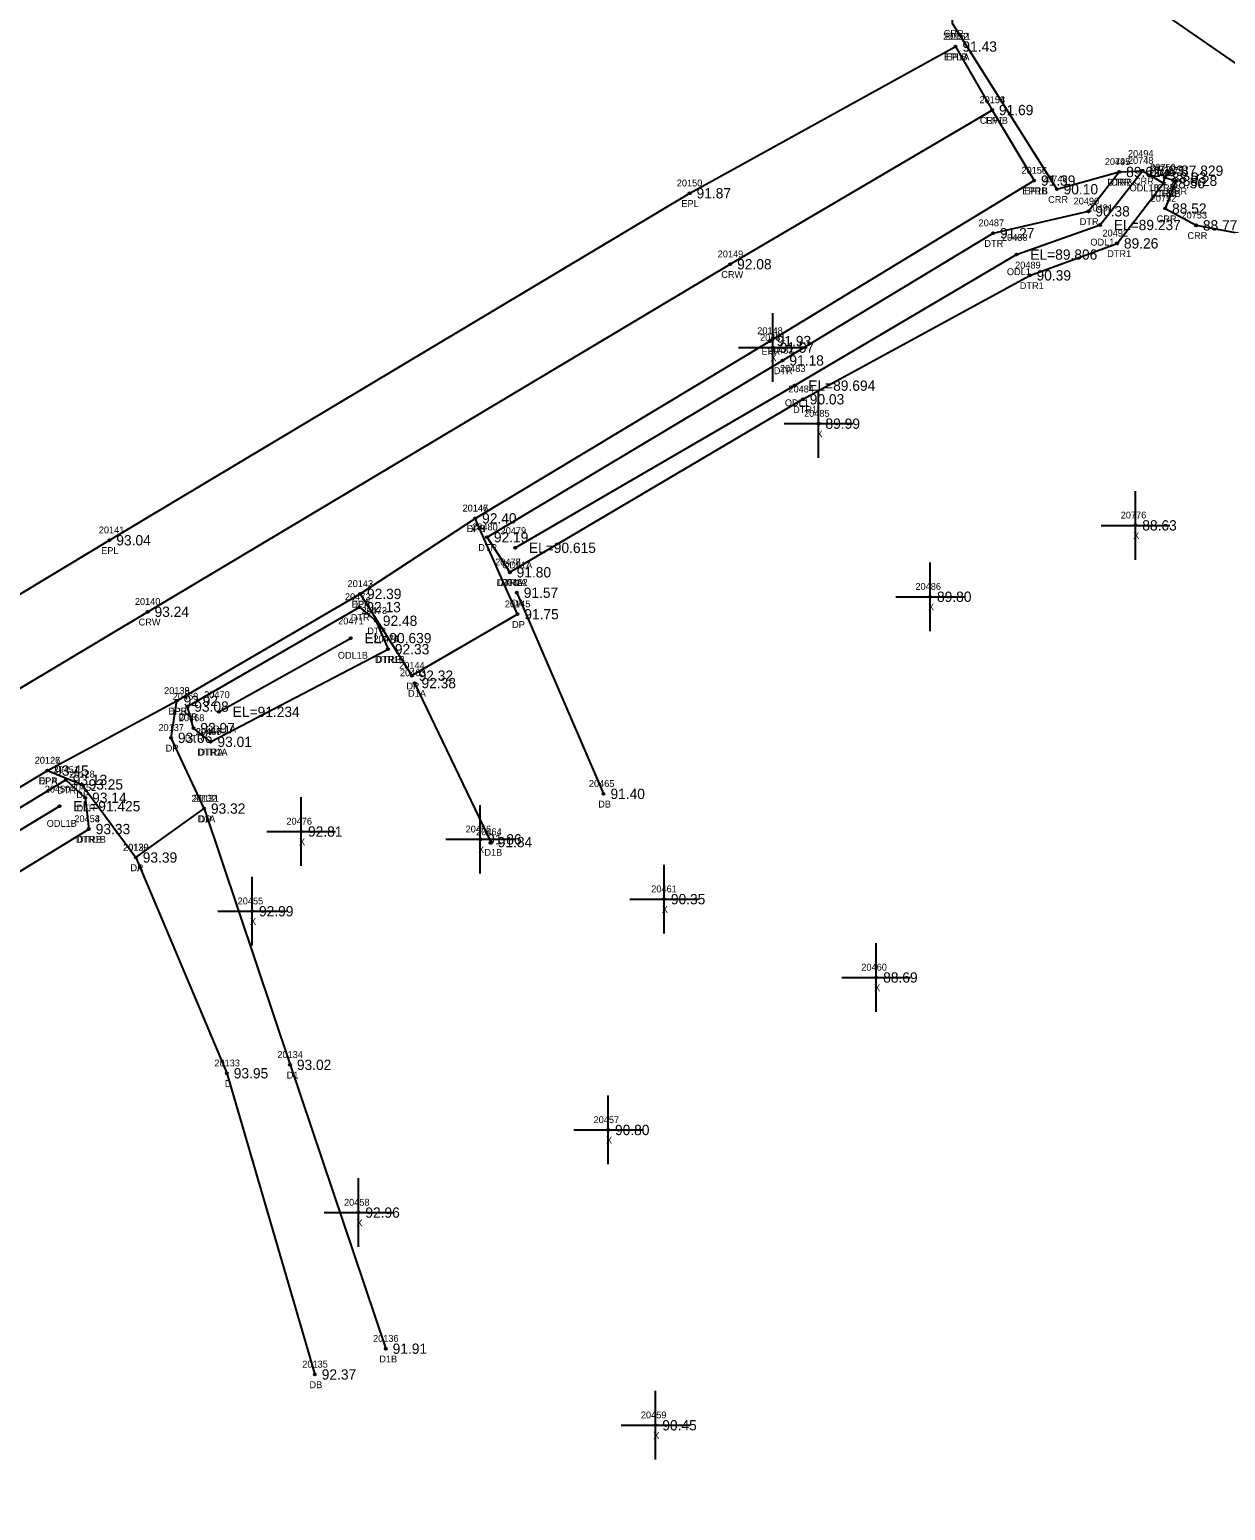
# Model space of a CAD drawing. Extents: x 2530197 to 2532051, y 935230 to 936631.
# Drawn here: x 2530944.6 to 2531118.7, y 935734.5 to 935950.2 of the extents above; entities that cross this region are included whole.
import ezdxf

# ---------------------------------------------------------------- set-up
doc = ezdxf.new("R2010")
doc.units = 0
for name, color, linetype in [('RD_DTM_BkLn1', 7, 'Continuous'), ('RD_EX_Driveway', 7, 'Continuous'), ('RD_EX_Driveway_txCode', 7, 'Continuous'), ('RD_EX_H2O', 7, 'Continuous'), ('RD_EX_H2O_txCode', 7, 'Continuous'), ('RD_EX_Misc', 7, 'Continuous'), ('RD_EX_Misc_txCode', 7, 'Continuous'), ('RD_EX_Road', 7, 'Continuous'), ('RD_EX_Road_txCode', 7, 'Continuous'), ('RD_EX_TX_Driveway_ELEV', 7, 'Continuous'), ('RD_EX_TX_H2O_ELEV', 7, 'Continuous'), ('RD_EX_TX_Misc_ELEV', 7, 'Continuous'), ('RD_EX_TX_Road_ELEV', 7, 'Continuous'), ('RD_HC_Survey_ELEV', 7, 'Continuous'), ('RD_HC_Survey_txCode', 7, 'Continuous'), ('RD_SMD_Locator', 7, 'Continuous')]:
    doc.layers.add(name, color=color, linetype=linetype)

msp = doc.modelspace()

# ---------------------------------------------------------------- linework, layer by layer
at = {"layer": 'RD_DTM_BkLn1'}
msp.add_lwpolyline([(2530212.5, 935590.24), (2530312.97, 935590.25), (2530414.21, 935590.57), (2530470.01, 935593.88), (2530526.51, 935611.77), (2530574.01, 935635.84), (2530615.35, 935659.73), (2530701.7, 935710.7), (2530789.3, 935762.35), (2530874.46, 935813.14), (2530961.78, 935865.4), (2531046.63, 935916.04), (2531084.76, 935938.51)], dxfattribs=at)
at = {"layer": 'RD_EX_Driveway'}
for p, q in [((2531015.55, 935868.18), (2531028.18, 935838.87)), ((2531000.66, 935855.01), (2531011.76, 935831.84))]:
    msp.add_line(p, q, dxfattribs=at)
for points in [[(2530992.72, 935868), (2531000.24, 935856.09), (2531015.63, 935865.04), (2531009.49, 935879.01)], [(2530947.17, 935842.26), (2530952.17, 935840.24), (2530960.06, 935829.59), (2530969.99, 935836.72), (2530965.18, 935847.03), (2530966, 935852.42)], [(2530969.99, 935836.72), (2530982.51, 935799.38), (2530996.46, 935758.02)], [(2530960.06, 935829.59), (2530973.32, 935798.15), (2530986.13, 935754.26)]]:
    msp.add_lwpolyline(points, dxfattribs=at)
at = {"layer": 'RD_EX_H2O'}
for p, q in [((2530970.94, 935846.45), (2530996.78, 935859.95)), ((2530972.16, 935850.82), (2530991.35, 935861.56)), ((2530886.58, 935799.6), (2530948.95, 935837.06))]:
    msp.add_line(p, q, dxfattribs=at)
for points in [[(2531095.07, 935962.75), (2531122.05, 935944.01), (2531139.42, 935896.32), (2531161, 935756.43), (2531179.99, 935655.36), (2531191.29, 935570.65), (2531207.98, 935448.59)], [(2531078.88, 935952.28), (2531078.96, 935951.18), (2531094.18, 935926.97), (2531103.29, 935929.49), (2531106.67, 935929.67), (2531109.75, 935927.85), (2531109.94, 935928.67), (2531111.53, 935928.19), (2531109.98, 935924.15), (2531114.47, 935921.71), (2531121.2, 935920.45), (2531134.65, 935891.6), (2531155.43, 935754.46), (2531173.73, 935652.91), (2531186.19, 935572.51), (2531201.43, 935446.7)], [(2531014.51, 935871.15), (2531011.2, 935876.26), (2531054.24, 935902.02), (2531084.91, 935920.57), (2531098.8, 935923.75), (2531103.29, 935929.49)], [(2531015.3, 935874.72), (2531055.99, 935898.35), (2531088.33, 935917.45), (2531100.49, 935921.76), (2531106.67, 935929.67)], [(2531014.51, 935871.15), (2531057.21, 935896.36), (2531090.24, 935914.42), (2531102.96, 935919.08), (2531109.75, 935927.85)], [(2530970.94, 935846.45), (2530968.45, 935848.45), (2530967.56, 935851.58), (2530992.63, 935866.08), (2530995.03, 935864.09), (2530996.78, 935859.95)], [(2530882.81, 935800.19), (2530949.87, 935840.9), (2530952.69, 935838.3), (2530953.21, 935833.74)], [(2530882.81, 935800.19), (2530888.21, 935794.65), (2530891.36, 935795.84), (2530953.21, 935833.74)]]:
    msp.add_lwpolyline(points, dxfattribs=at)
at = {"layer": 'RD_EX_Misc'}
for p, q in [((2531052.81, 935898.89), (2531052.81, 935908.89)), ((2531047.81, 935903.89), (2531057.81, 935903.89)), ((2531059.5, 935887.81), (2531059.5, 935897.81)), ((2531054.5, 935892.81), (2531064.5, 935892.81)), ((2531105.64, 935872.99), (2531105.64, 935882.99)), ((2531100.64, 935877.99), (2531110.64, 935877.99)), ((2531075.74, 935862.59), (2531075.74, 935872.59)), ((2531070.74, 935867.59), (2531080.74, 935867.59)), ((2530984.13, 935828.38), (2530984.13, 935838.38)), ((2531010.22, 935827.24), (2531010.22, 935837.24)), ((2530979.13, 935833.38), (2530989.13, 935833.38)), ((2531005.22, 935832.24), (2531015.22, 935832.24)), ((2531036.98, 935818.52), (2531036.98, 935828.52)), ((2530976.99, 935816.76), (2530976.99, 935826.76)), ((2531031.98, 935823.52), (2531041.98, 935823.52)), ((2530971.99, 935821.76), (2530981.99, 935821.76)), ((2531067.9, 935807.11), (2531067.9, 935817.11)), ((2531062.9, 935812.11), (2531072.9, 935812.11)), ((2531028.84, 935784.89), (2531028.84, 935794.89)), ((2531023.84, 935789.89), (2531033.84, 935789.89)), ((2530992.48, 935772.85), (2530992.48, 935782.85)), ((2530987.48, 935777.85), (2530997.48, 935777.85)), ((2531035.73, 935741.86), (2531035.73, 935751.86)), ((2531030.73, 935746.86), (2531040.73, 935746.86))]:
    msp.add_line(p, q, dxfattribs=at)
at = {"layer": 'RD_EX_Road'}
for points in [[(2530213.13, 935600.16), (2530313.8, 935600.81), (2530414.15, 935601.13), (2530426.72, 935601.43), (2530429.46, 935603.55), (2530467.67, 935608.62), (2530486.46, 935612.38), (2530518.02, 935622.55), (2530522.16, 935623.68), (2530567.91, 935646.01), (2530609.3, 935670.15), (2530695.46, 935720.02), (2530775.85, 935769.27), (2530868.29, 935824.03), (2530924.84, 935856.95), (2530956.21, 935875.82), (2531040.72, 935926.38), (2531079.45, 935947.76)], [(2531079.45, 935947.76), (2531084.76, 935938.51), (2531090.88, 935928.23)], [(2530212.44, 935579.72), (2530312.61, 935580.14), (2530402.98, 935580.64), (2530451.06, 935579.53), (2530466.91, 935580.35), (2530487.45, 935583.29), (2530533.43, 935598.45), (2530580.28, 935625.08), (2530621.69, 935649.23), (2530704.62, 935698.35), (2530718.67, 935706.38), (2530795.45, 935752.36), (2530871.33, 935796.67), (2530882.4, 935803.04), (2530947.17, 935842.26), (2530966, 935852.42), (2530992.72, 935868), (2531009.49, 935879.01), (2531052.39, 935904.85), (2531090.88, 935928.23)]]:
    msp.add_lwpolyline(points, dxfattribs=at)
at = {"layer": 'RD_SMD_Locator'}
for centre in [(2531079.45, 935947.76), (2531079.45, 935947.76), (2531084.76, 935938.51), (2531084.76, 935938.51), (2531103.29, 935929.49), (2531103.29, 935929.49), (2531106.67, 935929.67), (2531106.67, 935929.67), (2531109.94, 935928.67), (2531040.72, 935926.38), (2531090.88, 935928.23), (2531090.88, 935928.23), (2531094.18, 935926.97), (2531109.75, 935927.85), (2531109.75, 935927.85), (2531111.53, 935928.19), (2531109.98, 935924.15), (2531098.8, 935923.75), (2531084.91, 935920.57), (2531100.49, 935921.76), (2531114.47, 935921.71), (2531102.96, 935919.08), (2531046.63, 935916.04), (2531088.33, 935917.45), (2531090.24, 935914.42), (2531052.39, 935904.85), (2531052.81, 935903.89), (2531054.24, 935902.02), (2531055.99, 935898.35), (2531057.21, 935896.36), (2531059.5, 935892.81), (2531009.49, 935879.01), (2531009.49, 935879.01), (2531105.64, 935877.99), (2530956.21, 935875.82), (2531011.2, 935876.26), (2531015.3, 935874.72), (2531014.51, 935871.15), (2531014.51, 935871.15), (2530992.72, 935868), (2530992.72, 935868), (2531015.55, 935868.18), (2530992.63, 935866.08), (2531075.74, 935867.59), (2530961.78, 935865.4), (2530995.03, 935864.09), (2531015.63, 935865.04), (2530991.35, 935861.56), (2530996.78, 935859.95), (2530996.78, 935859.95), (2531000.24, 935856.09), (2531000.66, 935855.01), (2530966, 935852.42), (2530966, 935852.42), (2530967.56, 935851.58), (2530972.16, 935850.82), (2530965.18, 935847.03), (2530968.45, 935848.45), (2530970.94, 935846.45), (2530970.94, 935846.45), (2530947.17, 935842.26), (2530947.17, 935842.26), (2530949.87, 935840.9), (2530952.17, 935840.24), (2530952.69, 935838.3), (2531028.18, 935838.87), (2530948.95, 935837.06), (2530969.99, 935836.72), (2530969.99, 935836.72), (2530953.21, 935833.74), (2530953.21, 935833.74), (2530984.13, 935833.38), (2531010.22, 935832.24), (2531011.76, 935831.84), (2530960.06, 935829.59), (2530960.06, 935829.59), (2531036.98, 935823.52), (2530976.99, 935821.76), (2531067.9, 935812.11), (2530982.51, 935799.38), (2530973.32, 935798.15), (2531028.84, 935789.89), (2530992.48, 935777.85), (2530996.46, 935758.02), (2530986.13, 935754.26), (2531035.73, 935746.86)]:
    msp.add_circle(centre, 0.15, dxfattribs=at)

# ---------------------------------------------------------------- texts
at = {"layer": 'RD_EX_Driveway_txCode'}
for s, p in [('20146', (2531007.63, 935880.01)), ('DPB', (2531008.24, 935877.01)), ('20143', (2530990.89, 935869)), ('20462', (2531013.41, 935869.18)), ('DPA', (2530991.46, 935866)), ('20145', (2531013.8, 935866.04)), ('DA', (2531014.76, 935866.18)), ('DP', (2531014.85, 935863.04)), ('20144', (2530998.4, 935857.09)), ('20463', (2530998.52, 935856.01)), ('20138', (2530964.17, 935853.42)), ('DP', (2530999.46, 935854.09)), ('D1A', (2530999.7, 935853.01)), ('DPB', (2530964.75, 935850.42)), ('20137', (2530963.34, 935848.03)), ('DP', (2530964.4, 935845.03)), ('20127', (2530945.33, 935843.26)), ('20128', (2530950.34, 935841.24)), ('DPA', (2530945.9, 935840.26)), ('20465', (2531026.04, 935839.87)), ('DP', (2530951.39, 935838.24)), ('20132', (2530968.16, 935837.72)), ('20131', (2530968.44, 935837.72)), ('D1A', (2530969.03, 935834.72)), ('DP', (2530969.21, 935834.72)), ('DB', (2531027.4, 935836.87)), ('20464', (2531009.62, 935832.84)), ('20130', (2530958.18, 935830.59)), ('20129', (2530958.22, 935830.59)), ('D1B', (2531010.82, 935829.84)), ('DA', (2530959.26, 935827.59)), ('DP', (2530959.28, 935827.59)), ('20134', (2530980.67, 935800.38)), ('20133', (2530971.49, 935799.15)), ('D', (2530973.02, 935796.15)), ('D1', (2530982.03, 935797.38)), ('20136', (2530994.6, 935759.02)), ('20135', (2530984.3, 935755.26)), ('D1B', (2530995.51, 935756.02)), ('DB', (2530985.35, 935752.26))]:
    msp.add_text(s, height=1, dxfattribs=at).set_placement(p)
at = {"layer": 'RD_EX_H2O_txCode'}
for s, p in [('CRR', (2531077.71, 935949.18)), ('20495', (2531101.18, 935930.49)), ('20747', (2531101.18, 935930.49)), ('20494', (2531104.55, 935931.67)), ('20748', (2531104.55, 935930.67)), ('20750', (2531107.78, 935929.67)), ('20746', (2531092.04, 935927.97)), ('CRR', (2531102.04, 935927.49)), ('CRR', (2531105.42, 935927.67)), ('20493', (2531107.63, 935928.85)), ('20749', (2531107.63, 935928.85)), ('20751', (2531109.69, 935929.19)), ('DTRB', (2531101.55, 935927.49)), ('ODL1B', (2531104.79, 935926.67)), ('DTR1B', (2531107.85, 935925.85)), ('CRR', (2531108.5, 935925.85)), ('CRR', (2531108.69, 935926.67)), ('CRR', (2531110.28, 935926.19)), ('CRR', (2531092.93, 935924.97)), ('20490', (2531096.64, 935924.75)), ('20491', (2531098.65, 935923.76)), ('20752', (2531107.87, 935925.15)), ('20487', (2531082.79, 935921.57)), ('DTR', (2531097.53, 935921.75)), ('CRR', (2531108.73, 935922.15)), ('20753', (2531112.35, 935922.71)), ('20488', (2531086.21, 935919.45)), ('20492', (2531100.84, 935920.08)), ('CRR', (2531113.22, 935919.71)), ('DTR', (2531083.64, 935918.57)), ('ODL1', (2531099.08, 935918.76)), ('DTR1', (2531101.53, 935917.08)), ('20489', (2531088.12, 935915.42)), ('ODL1', (2531086.92, 935914.45)), ('DTR1', (2531088.8, 935912.42)), ('20482', (2531052.12, 935903.02)), ('DTR', (2531052.97, 935900.02)), ('20483', (2531053.87, 935900.35)), ('20484', (2531055.1, 935897.36)), ('ODL1', (2531054.58, 935895.35)), ('DTR1', (2531055.78, 935894.36)), ('20480', (2531009.04, 935877.26)), ('20479', (2531013.18, 935876.72)), ('DTR', (2531009.93, 935874.26)), ('20477', (2531012.39, 935872.15)), ('20478', (2531012.39, 935872.15)), ('ODL1A', (2531013.4, 935871.72)), ('20472', (2530990.51, 935867.08)), ('DTR1A', (2531012.59, 935869.15)), ('DTRA', (2531012.76, 935869.15)), ('20473', (2530992.91, 935865.09)), ('20471', (2530989.52, 935863.56)), ('DTR', (2530991.36, 935864.08)), ('DTR', (2530993.76, 935862.09)), ('20474', (2530994.66, 935860.95)), ('20475', (2530994.66, 935860.95)), ('ODL1B', (2530989.47, 935858.56)), ('DTR1B', (2530994.87, 935857.95)), ('DTRB', (2530995.04, 935857.95)), ('20469', (2530965.42, 935852.58)), ('20470', (2530970, 935852.82)), ('20468', (2530966.31, 935849.45)), ('DTR', (2530966.29, 935849.58)), ('ODL1A', (2530970.26, 935847.82)), ('DTR', (2530967.18, 935846.45)), ('20466', (2530968.77, 935847.45)), ('20467', (2530968.8, 935847.45)), ('DTR1A', (2530969.02, 935844.45)), ('DTRA', (2530969.18, 935844.45)), ('20451', (2530948.04, 935841.9)), ('20450', (2530946.79, 935839.06)), ('20452', (2530950.57, 935839.3)), ('DTR', (2530948.61, 935838.9)), ('20453', (2530951.1, 935834.74)), ('20454', (2530951.1, 935834.74)), ('DTR', (2530951.42, 935836.3)), ('ODL1B', (2530947.07, 935834.06)), ('DTR1B', (2530951.31, 935831.74)), ('DTRB', (2530951.47, 935831.74))]:
    msp.add_text(s, height=1, dxfattribs=at).set_placement(p)
at = {"layer": 'RD_EX_Misc_txCode'}
for s, p in [('20481', (2531050.97, 935904.89)), ('X', (2531052.49, 935901.89)), ('20485', (2531057.38, 935893.81)), ('X', (2531059.19, 935890.81)), ('20776', (2531103.5, 935878.99)), ('X', (2531105.32, 935875.99)), ('20486', (2531073.6, 935868.59)), ('X', (2531075.43, 935865.59)), ('20476', (2530981.99, 935834.38)), ('20456', (2531008.08, 935833.24)), ('X', (2530983.81, 935831.38)), ('X', (2531009.9, 935830.24)), ('20461', (2531035.12, 935824.52)), ('20455', (2530974.88, 935822.76)), ('X', (2530976.68, 935819.76)), ('X', (2531036.66, 935821.52)), ('20460', (2531065.72, 935813.11)), ('X', (2531067.58, 935810.11)), ('20457', (2531026.72, 935790.89)), ('X', (2531028.53, 935787.89)), ('20458', (2530990.37, 935778.85)), ('X', (2530992.17, 935775.85)), ('20459', (2531033.61, 935747.86)), ('X', (2531035.42, 935744.86))]:
    msp.add_text(s, height=1, dxfattribs=at).set_placement(p)
at = {"layer": 'RD_EX_Road_txCode'}
for s, p in [('20152', (2531077.62, 935948.76)), ('20151', (2531077.9, 935948.76)), ('EPLB', (2531077.77, 935945.76)), ('EP1A', (2531078.04, 935945.76)), ('20153', (2531082.93, 935939.51)), ('EP1', (2531083.84, 935936.51)), ('20156', (2531089.03, 935929.23)), ('20155', (2531089.05, 935929.23)), ('20150', (2531038.84, 935927.38)), ('EPRB', (2531089.18, 935926.23)), ('EP1B', (2531089.49, 935926.23)), ('EPL', (2531039.51, 935924.38)), ('20148', (2531050.56, 935905.85)), ('EPR', (2531051.17, 935902.85)), ('20147', (2531007.65, 935880.01)), ('20141', (2530954.66, 935876.82)), ('EPR', (2531008.26, 935877.01)), ('EPL', (2530955, 935873.82)), ('20142', (2530990.89, 935869)), ('EPR', (2530991.5, 935866)), ('20139', (2530964.17, 935853.42)), ('EPR', (2530964.77, 935850.42)), ('20126', (2530945.31, 935843.26)), ('EPR', (2530945.94, 935840.26))]:
    msp.add_text(s, height=1, dxfattribs=at).set_placement(p)
at = {"layer": 'RD_EX_TX_Driveway_ELEV'}
for s, p in [('92.40', (2531010.49, 935878.26)), ('92.39', (2530993.72, 935867.25)), ('91.57', (2531016.55, 935867.43)), ('91.75', (2531016.63, 935864.29)), ('92.32', (2531001.24, 935855.34)), ('92.38', (2531001.66, 935854.26)), ('92.92', (2530967, 935851.67)), ('93.06', (2530966.18, 935846.28)), ('93.45', (2530948.17, 935841.51)), ('93.25', (2530953.17, 935839.49)), ('91.40', (2531029.18, 935838.12)), ('93.32', (2530970.99, 935835.97)), ('93.32', (2530970.99, 935835.97)), ('91.84', (2531012.76, 935831.09)), ('93.39', (2530961.06, 935828.84)), ('93.39', (2530961.06, 935828.84)), ('93.02', (2530983.51, 935798.63)), ('93.95', (2530974.32, 935797.4)), ('91.91', (2530997.46, 935757.27)), ('92.37', (2530987.13, 935753.51))]:
    msp.add_text(s, height=1.5, dxfattribs=at).set_placement(p)
at = {"layer": 'RD_EX_TX_H2O_ELEV'}
for s, p in [('89.62', (2531104.29, 935928.74)), ('89.62', (2531104.29, 935928.74)), ('87.83', (2531107.67, 935928.92)), ('EL=87.829', (2531108.67, 935928.92)), ('88.56', (2531110.75, 935927.1)), ('88.56', (2531110.75, 935927.1)), ('88.03', (2531110.94, 935927.92)), ('88.28', (2531112.53, 935927.44)), ('90.10', (2531095.18, 935926.22)), ('90.38', (2531099.8, 935923)), ('88.52', (2531110.98, 935923.4)), ('EL=89.237', (2531102.49, 935921.01)), ('88.77', (2531115.47, 935920.96)), ('91.27', (2531085.91, 935919.82)), ('EL=89.806', (2531090.33, 935916.7)), ('89.26', (2531103.96, 935918.33)), ('90.39', (2531091.24, 935913.67)), ('91.18', (2531055.24, 935901.27)), ('EL=89.694', (2531057.99, 935897.6)), ('90.03', (2531058.21, 935895.61)), ('92.19', (2531012.2, 935875.51)), ('EL=90.615', (2531017.3, 935873.97)), ('91.80', (2531015.51, 935870.4)), ('91.80', (2531015.51, 935870.4)), ('92.13', (2530993.63, 935865.33)), ('92.48', (2530996.03, 935863.34)), ('EL=90.639', (2530993.35, 935860.81)), ('92.33', (2530997.78, 935859.2)), ('92.33', (2530997.78, 935859.2)), ('93.08', (2530968.56, 935850.83)), ('EL=91.234', (2530974.16, 935850.07)), ('92.97', (2530969.45, 935847.7)), ('93.01', (2530971.94, 935845.7)), ('93.01', (2530971.94, 935845.7)), ('93.13', (2530950.87, 935840.15)), ('93.14', (2530953.69, 935837.55)), ('EL=91.425', (2530950.95, 935836.31)), ('93.33', (2530954.21, 935832.99)), ('93.33', (2530954.21, 935832.99))]:
    msp.add_text(s, height=1.5, dxfattribs=at).set_placement(p)
at = {"layer": 'RD_EX_TX_Misc_ELEV'}
for s, p in [('91.57', (2531053.81, 935903.14)), ('89.99', (2531060.5, 935892.06)), ('88.63', (2531106.64, 935877.24)), ('89.80', (2531076.74, 935866.84)), ('92.81', (2530985.13, 935832.63)), ('91.86', (2531011.22, 935831.49)), ('90.35', (2531037.98, 935822.77)), ('92.99', (2530977.99, 935821.01)), ('88.69', (2531068.9, 935811.36)), ('90.80', (2531029.84, 935789.14)), ('92.96', (2530993.48, 935777.1)), ('90.45', (2531036.73, 935746.11))]:
    msp.add_text(s, height=1.5, dxfattribs=at).set_placement(p)
at = {"layer": 'RD_EX_TX_Road_ELEV'}
for s, p in [('91.43', (2531080.45, 935947.01)), ('91.43', (2531080.45, 935947.01)), ('91.69', (2531085.76, 935937.76)), ('91.39', (2531091.88, 935927.48)), ('91.39', (2531091.88, 935927.48)), ('91.87', (2531041.72, 935925.63)), ('91.93', (2531053.39, 935904.1)), ('92.40', (2531010.49, 935878.26)), ('93.04', (2530957.21, 935875.07)), ('92.39', (2530993.72, 935867.25)), ('92.92', (2530967, 935851.67)), ('93.45', (2530948.17, 935841.51))]:
    msp.add_text(s, height=1.5, dxfattribs=at).set_placement(p)
at = {"layer": 'RD_HC_Survey_ELEV'}
for s, p in [('91.69', (2531085.76, 935937.76)), ('92.08', (2531047.63, 935915.29)), ('93.24', (2530962.78, 935864.65))]:
    msp.add_text(s, height=1.5, dxfattribs=at).set_placement(p)
at = {"layer": 'RD_HC_Survey_txCode'}
for s, p in [('20154', (2531082.93, 935939.51)), ('CRWB', (2531082.98, 935936.51)), ('20149', (2531044.8, 935917.04)), ('CRW', (2531045.32, 935914.04)), ('20140', (2530959.91, 935866.4)), ('CRW', (2530960.46, 935863.4))]:
    msp.add_text(s, height=1, dxfattribs=at).set_placement(p)

doc.saveas('drawing.dxf')
